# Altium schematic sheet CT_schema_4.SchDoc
size 383 x 218 mm
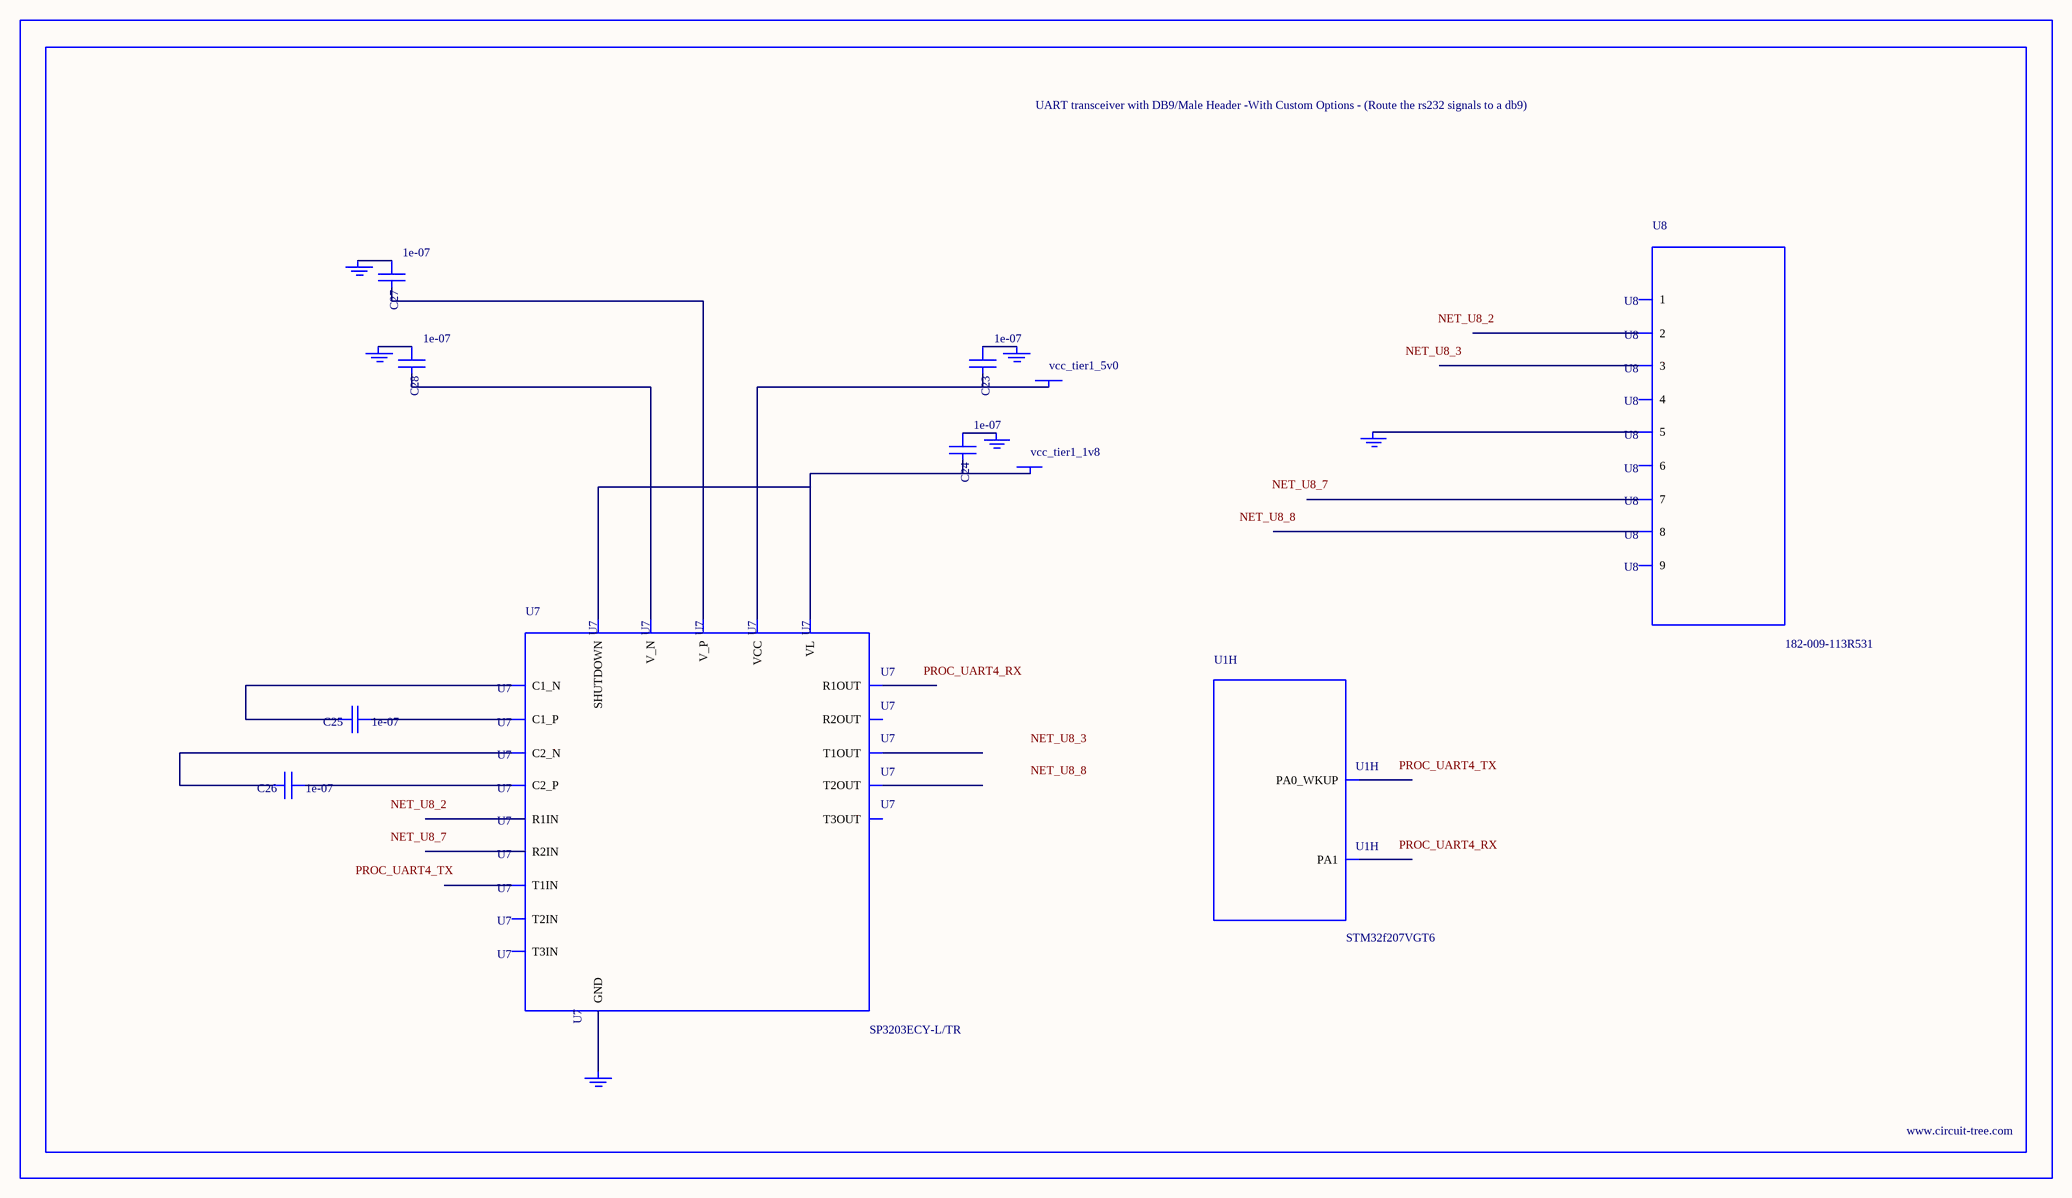
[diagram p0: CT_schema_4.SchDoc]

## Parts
BORDER3  (no value)
C23  1e-07  [C0402]
C24  1e-07  [C0402]
C25  1e-07  [C0402]
C26  1e-07  [C0402]
C27  1e-07  [C0402]
C28  1e-07  [C0402]
GND_INSTANCE_3_0  (no value)
GND_INSTANCE_3_1  (no value)
GND_INSTANCE_3_2  (no value)
GND_INSTANCE_3_3  (no value)
GND_INSTANCE_3_4  (no value)
GND_INSTANCE_3_5  (no value)
POWER_INSTANCE_3_0  vcc_tier1_1v8
POWER_INSTANCE_3_1  vcc_tier1_5v0
U1  STM32f207VGT6  [LQFP100]  (part H of 10)
U7  SP3203ECY-L/TR  [TSSOP20-I]
U8  182-009-113R531  [182-009-MALE]

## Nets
NetC23_1: C23.1 GND_INSTANCE_3_3.0(GND)
NetC23_2: C23.2 POWER_INSTANCE_3_1.0(PWR) U7.19(VCC)
NetC24_1: C24.1 GND_INSTANCE_3_2.0(GND)
NetC24_2: C24.2 POWER_INSTANCE_3_0.0(PWR) U7.12(VL) U7.20(SHUTDOWN)
NetC25_1: C25.1 U7.1(C1_P)
NetC25_2: C25.2 U7.3(C1_N)
NetC26_1: C26.1 U7.4(C2_P)
NetC26_2: C26.2 U7.5(C2_N)
NetC27_1: C27.1 GND_INSTANCE_3_0.0(GND)
NetC27_2: C27.2 U7.2(V_P)
NetC28_1: C28.1 GND_INSTANCE_3_1.0(GND)
NetC28_2: C28.2 U7.6(V_N)
NetGND_INSTANCE_3_4_0: GND_INSTANCE_3_4.0(GND) U7.18(GND)
NetGND_INSTANCE_3_5_0: GND_INSTANCE_3_5.0(GND) U8.5

Not connected (* = marked no-connect by the designer): U1 23(PA0_WKUP) 24(PA1); U7 7(T1IN) 8(T2IN) 9(T3IN) 10(R2OUT) 11(R1OUT) 13(R2IN) 14(R1IN) 15(T3OUT) 16(T2OUT) 17(T1OUT); U8 1 2 3 4 6 7 8 9

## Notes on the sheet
- Labels drawn without touching a wire or pin: NET_U8_2, NET_U8_3, NET_U8_7, NET_U8_8, PROC_UART4_RX, PROC_UART4_TX

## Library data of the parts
BORDER3 = BORDER_PAGE3
C23-C28 = C0402C104K3RACTU
GND_INSTANCE_3_0-GND_INSTANCE_3_5 = GND
POWER_INSTANCE_3_0 POWER_INSTANCE_3_1 = PWR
